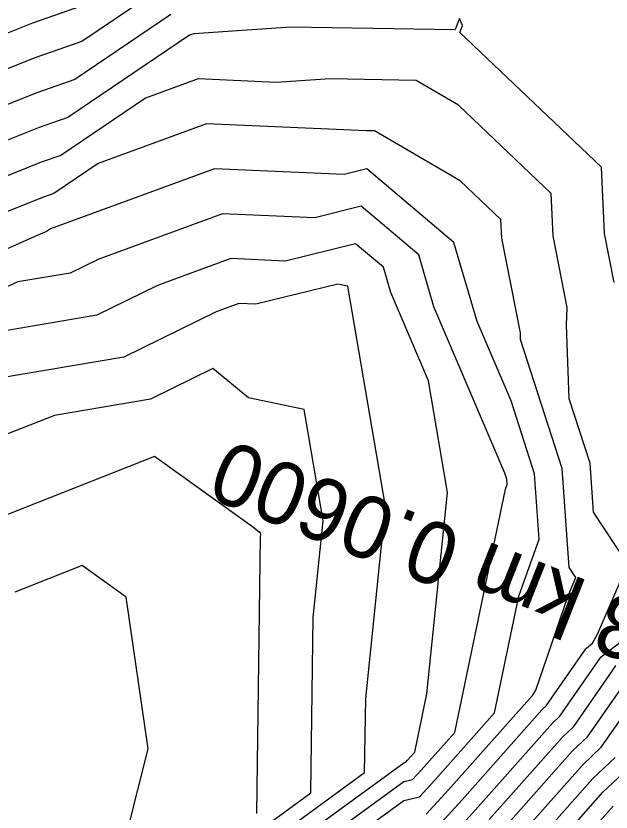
# Model space of a CAD drawing. Extents: x -549394 to -546608, y -1037055 to -1033629.
# Drawn here: x -547735.2 to -547648.7, y -1035700.8 to -1035584.9 of the extents above; entities that cross this region are included whole.
import ezdxf

# ---------------------------------------------------------------- set-up
doc = ezdxf.new("R2010")
doc.units = 0
for name, color, linetype in [('hlavni_vrst', 7, 'Continuous'), ('norm_vrst', 7, 'Continuous'), ('x_popis_pricne_rezy_C111', 7, 'Continuous')]:
    doc.layers.add(name, color=color, linetype=linetype)

msp = doc.modelspace()

# ---------------------------------------------------------------- linework, layer by layer
at = {"layer": 'hlavni_vrst'}
for p, q in [((-547708.68, -1035594.07), (-547716.35, -1035596.89)), ((-547697.34, -1035594.58), (-547708.68, -1035594.07)), ((-547689.5, -1035594.07), (-547697.34, -1035594.58)), ((-547677.03, -1035594.3), (-547689.5, -1035594.07)), ((-547670.86, -1035597.91), (-547677.03, -1035594.3)), ((-547716.35, -1035596.89), (-547728.69, -1035605.22)), ((-547657.37, -1035610.73), (-547670.86, -1035597.91)), ((-547728.69, -1035605.22), (-547731.51, -1035606.21)), ((-547731.51, -1035606.21), (-547746.38, -1035612.11)), ((-547657.09, -1035616.91), (-547657.37, -1035610.73)), ((-547655.03, -1035627.36), (-547657.09, -1035616.91)), ((-547688.42, -1035623.94), (-547700.33, -1035626.88)), ((-547686.95, -1035624.25), (-547688.42, -1035623.94)), ((-547681.49, -1035656.31), (-547686.95, -1035624.25)), ((-547702.79, -1035626.77), (-547706.1, -1035627.98)), ((-547700.33, -1035626.88), (-547702.79, -1035626.77)), ((-547655.15, -1035629.91), (-547655.03, -1035627.36)), ((-547706.1, -1035627.98), (-547719.52, -1035634.57)), ((-547654.74, -1035640.65), (-547655.15, -1035629.91)), ((-547719.52, -1035634.57), (-547743.94, -1035638.7)), ((-547651.72, -1035649.98), (-547654.74, -1035640.65)), ((-547651.21, -1035657.15), (-547651.72, -1035649.98)), ((-547684.35, -1035684.25), (-547681.49, -1035656.31)), ((-547646.23, -1035664.72), (-547651.21, -1035657.15)), ((-547650.62, -1035674.87), (-547646.23, -1035664.72)), ((-547651.38, -1035676.22), (-547650.62, -1035674.87)), ((-547658.11, -1035685.31), (-547652.34, -1035677.01)), ((-547652.34, -1035677.01), (-547652.26, -1035676.9)), ((-547652.26, -1035676.9), (-547651.38, -1035676.22)), ((-547684.5, -1035695.02), (-547684.35, -1035684.25)), ((-547658.68, -1035685.86), (-547658.11, -1035685.31)), ((-547670.34, -1035698.99), (-547658.68, -1035685.86)), ((-547651.32, -1035695.89), (-547648.09, -1035692.84)), ((-547702.16, -1035707.89), (-547684.5, -1035695.02)), ((-547660.47, -1035706.19), (-547651.32, -1035695.89)), ((-547674.55, -1035703.62), (-547670.34, -1035698.99))]:
    msp.add_line(p, q, dxfattribs=at)
at = {"layer": 'norm_vrst'}
for p, q in [((-547715.4, -1035581.71), (-547725.61, -1035588.62)), ((-547724.58, -1035583.08), (-547732.77, -1035585.94)), ((-547712.67, -1035584.71), (-547726.64, -1035594.15)), ((-547670.71, -1035585.26), (-547671.25, -1035586.64)), ((-547670.29, -1035586.31), (-547670.71, -1035585.26)), ((-547732.77, -1035585.94), (-547747.09, -1035591.62)), ((-547695.23, -1035586.53), (-547709.31, -1035587.5)), ((-547695.23, -1035586.53), (-547695.23, -1035586.53)), ((-547695.23, -1035586.53), (-547695.23, -1035586.53)), ((-547671.39, -1035586.93), (-547695.23, -1035586.53)), ((-547695.23, -1035586.53), (-547695.23, -1035586.53)), ((-547695.23, -1035586.53), (-547695.23, -1035586.53)), ((-547671.32, -1035586.86), (-547671.39, -1035586.93)), ((-547671.25, -1035586.64), (-547671.32, -1035586.86)), ((-547670.67, -1035587.33), (-547670.29, -1035586.31)), ((-547709.94, -1035587.71), (-547727.66, -1035599.69)), ((-547709.31, -1035587.5), (-547709.94, -1035587.71)), ((-547650.05, -1035606.93), (-547670.67, -1035587.33)), ((-547725.61, -1035588.62), (-547732.46, -1035591.01)), ((-547732.46, -1035591.01), (-547751.11, -1035598.41)), ((-547726.64, -1035594.15), (-547732.14, -1035596.08)), ((-547732.14, -1035596.08), (-547755.13, -1035605.19)), ((-547727.66, -1035599.69), (-547731.82, -1035601.14)), ((-547707.5, -1035600.61), (-547723.25, -1035606.39)), ((-547684.22, -1035601.65), (-547707.5, -1035600.61)), ((-547731.82, -1035601.14), (-547753.78, -1035609.85)), ((-547683.77, -1035601.62), (-547684.22, -1035601.65)), ((-547683.07, -1035601.63), (-547683.77, -1035601.62)), ((-547670.6, -1035608.91), (-547683.07, -1035601.63)), ((-547723.25, -1035606.39), (-547729.71, -1035610.76)), ((-547706.32, -1035607.15), (-547730.15, -1035615.9)), ((-547687.46, -1035607.99), (-547706.32, -1035607.15)), ((-547684.19, -1035607.18), (-547687.46, -1035607.99)), ((-547671.53, -1035617.89), (-547684.19, -1035607.18)), ((-547649.61, -1035616.58), (-547650.05, -1035606.93)), ((-547664.69, -1035614.53), (-547670.6, -1035608.91)), ((-547729.71, -1035610.76), (-547731.19, -1035611.28)), ((-547731.19, -1035611.28), (-547738.98, -1035614.37)), ((-547685, -1035612.62), (-547691.75, -1035614.28)), ((-547676.64, -1035619.69), (-547685, -1035612.62)), ((-547705.15, -1035613.69), (-547723.16, -1035620.3)), ((-547691.75, -1035614.28), (-547705.15, -1035613.69)), ((-547664.57, -1035617.24), (-547664.69, -1035614.53)), ((-547731.58, -1035616.62), (-547751.1, -1035625.27)), ((-547730.87, -1035616.34), (-547731.58, -1035616.62)), ((-547730.74, -1035616.3), (-547730.87, -1035616.34)), ((-547730.15, -1035615.9), (-547730.74, -1035616.3)), ((-547648.2, -1035623.7), (-547649.61, -1035616.58)), ((-547685.81, -1035618.06), (-547696.04, -1035620.58)), ((-547681.76, -1035621.48), (-547685.81, -1035618.06)), ((-547668.16, -1035629.37), (-547671.53, -1035617.89)), ((-547661.85, -1035631.02), (-547664.57, -1035617.24)), ((-547723.16, -1035620.3), (-547727.33, -1035622.35)), ((-547703.97, -1035620.23), (-547714.63, -1035624.14)), ((-547696.04, -1035620.58), (-547703.97, -1035620.23)), ((-547674.42, -1035627.26), (-547676.64, -1035619.69)), ((-547680.68, -1035625.15), (-547681.76, -1035621.48)), ((-547727.33, -1035622.35), (-547734.91, -1035623.63)), ((-547734.91, -1035623.63), (-547749.32, -1035630.02)), ((-547714.63, -1035624.14), (-547723.42, -1035628.46)), ((-547675.2, -1035638.01), (-547680.68, -1035625.15)), ((-547664.12, -1035651.44), (-547674.42, -1035627.26)), ((-547723.42, -1035628.46), (-547739.42, -1035631.17)), ((-547663.22, -1035640.95), (-547668.16, -1035629.37)), ((-547661.86, -1035631.21), (-547661.85, -1035631.02)), ((-547661.83, -1035632), (-547661.86, -1035631.21)), ((-547655.76, -1035650.76), (-547661.83, -1035632)), ((-547706.57, -1035636.24), (-547715.62, -1035640.68)), ((-547701.39, -1035640.49), (-547706.57, -1035636.24)), ((-547672.44, -1035654.25), (-547675.2, -1035638.01)), ((-547715.62, -1035640.68), (-547729.59, -1035643.04)), ((-547693.3, -1035642.18), (-547701.39, -1035640.49)), ((-547659.8, -1035651.53), (-547663.22, -1035640.95)), ((-547690.54, -1035658.37), (-547693.3, -1035642.18)), ((-547729.59, -1035643.04), (-547742.66, -1035648.19)), ((-547715.03, -1035649.03), (-547739.01, -1035658.48)), ((-547700.8, -1035659.26), (-547715.03, -1035649.03)), ((-547663.84, -1035652.31), (-547664.12, -1035651.44)), ((-547659.13, -1035661.05), (-547659.8, -1035651.53)), ((-547654.74, -1035665.17), (-547655.76, -1035650.76)), ((-547663.78, -1035653.1), (-547663.84, -1035652.31)), ((-547671.41, -1035689.2), (-547664.02, -1035653.78)), ((-547664.02, -1035653.78), (-547663.78, -1035653.1)), ((-547675.44, -1035683.59), (-547672.44, -1035654.25)), ((-547691.98, -1035672.48), (-547690.54, -1035658.37)), ((-547699.8, -1035660.08), (-547700.8, -1035659.26)), ((-547700.17, -1035700.98), (-547699.62, -1035660.71)), ((-547699.64, -1035660.11), (-547699.8, -1035660.08)), ((-547699.59, -1035660.43), (-547699.64, -1035660.11)), ((-547699.62, -1035660.71), (-547699.59, -1035660.43)), ((-547662.07, -1035669.36), (-547659.13, -1035661.05)), ((-547725.57, -1035664.91), (-547735.36, -1035668.77)), ((-547719.18, -1035669.51), (-547725.57, -1035664.91)), ((-547653.78, -1035666.64), (-547654.74, -1035665.17)), ((-547654.92, -1035669.29), (-547653.78, -1035666.64)), ((-547715.97, -1035691.59), (-547719.18, -1035669.51)), ((-547665.61, -1035686.33), (-547662.07, -1035669.36)), ((-547659.59, -1035683.06), (-547654.92, -1035669.29)), ((-547692.33, -1035698), (-547691.98, -1035672.48)), ((-547650.11, -1035678.18), (-547644.57, -1035673.93)), ((-547650.58, -1035678.88), (-547650.11, -1035678.18)), ((-547656.1, -1035686.82), (-547650.58, -1035678.88)), ((-547648.83, -1035680.74), (-547647.96, -1035679.46)), ((-547654.1, -1035688.32), (-547648.83, -1035680.74)), ((-547660.11, -1035683.81), (-547659.59, -1035683.06)), ((-547652.09, -1035689.83), (-547647.07, -1035682.6)), ((-547677.21, -1035692.07), (-547675.44, -1035683.59)), ((-547672.32, -1035697.56), (-547660.15, -1035683.85)), ((-547660.15, -1035683.85), (-547660.11, -1035683.81)), ((-547650.09, -1035691.33), (-547645.32, -1035684.46)), ((-547674.3, -1035696.12), (-547665.61, -1035686.33)), ((-547657.21, -1035687.86), (-547656.1, -1035686.82)), ((-547668.37, -1035700.43), (-547657.21, -1035687.86)), ((-547655.74, -1035689.87), (-547654.1, -1035688.32)), ((-547676.27, -1035694.68), (-547671.41, -1035689.2)), ((-547666.39, -1035701.87), (-547655.74, -1035689.87)), ((-547654.27, -1035691.88), (-547652.09, -1035689.83)), ((-547720.38, -1035708.96), (-547715.97, -1035691.59)), ((-547678.25, -1035693.24), (-547677.21, -1035692.07)), ((-547664.42, -1035703.31), (-547654.27, -1035691.88)), ((-547652.8, -1035693.89), (-547650.09, -1035691.33)), ((-547678.51, -1035693.53), (-547678.25, -1035693.24)), ((-547701.34, -1035710.02), (-547678.78, -1035693.59)), ((-547678.78, -1035693.59), (-547678.51, -1035693.53)), ((-547662.44, -1035704.75), (-547652.8, -1035693.89)), ((-547649.85, -1035697.9), (-547646.08, -1035694.34)), ((-547677.52, -1035696.05), (-547676.27, -1035694.68)), ((-547700.52, -1035712.14), (-547678.8, -1035696.33)), ((-547678.8, -1035696.33), (-547677.52, -1035696.05)), ((-547676.53, -1035698.58), (-547674.3, -1035696.12)), ((-547702.99, -1035705.76), (-547692.33, -1035698)), ((-547675.54, -1035701.1), (-547672.32, -1035697.56)), ((-547658.49, -1035707.63), (-547649.85, -1035697.9)), ((-547699.69, -1035714.27), (-547678.82, -1035699.07)), ((-547678.82, -1035699.07), (-547676.53, -1035698.58)), ((-547673.56, -1035706.14), (-547668.37, -1035700.43)), ((-547656.52, -1035709.07), (-547648.38, -1035699.91))]:
    msp.add_line(p, q, dxfattribs=at)

# ---------------------------------------------------------------- texts
at = {"layer": 'x_popis_pricne_rezy_C111'}
msp.add_text('PŘ 3 km 0.0600', height=9.0627, rotation=158.4447, dxfattribs=at).set_placement((-547623.58, -1035678.34))

doc.saveas('drawing.dxf')
